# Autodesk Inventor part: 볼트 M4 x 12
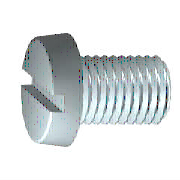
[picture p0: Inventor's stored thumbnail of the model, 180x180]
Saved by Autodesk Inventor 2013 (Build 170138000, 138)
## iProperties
Created: 2012-02
Part Number: 볼트 M4 x 12
Material: 강철, 연강
Description: 6각머리 태핑 나사
Document SubType Name: Modeling
Standard: KS B 1021
Designer: mduedu
Standards Organization: KS
Language: ko-KR
Size Designation: A  M 4 x 12
Categories: <MemberInstance><Categories><Category DisplayName="조임쇠" InternalName="e4da775c-781d-43d5-af7c-5136215cf5a6" Mnemonic="FSTN"><Category DisplayName="볼트" InternalN
Density: 1 g/cm^3
IsCustomPart: 0
Author: mduedu
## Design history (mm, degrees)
body "Solid1"
revolve "본체" stored, may be unused: angle "d8" = 90 deg
sketch "스케치2"
  geometry: L1 (0, 0)-(0, 3.273) reference; L2 (-3.5, 0.6)-(3.5, 0.6); L3 (3.5, 0.6)-(3.5, -0.6); L4 (3.5, -0.6)-(-3.5, -0.6); L5 (-3.5, -0.6)-(-3.5, 0.6); L6 (-3.5, 0)-(3.5, 0); L7 (0, 0.6)-(0, -0.6); C1 r 3.5 at (0, 0) reference; 1 further point
  constraints: 12 end point, 5 midpoint, 2 parallel, 1 collinear, 1 horizontal, 1 perpendicular
  dimensions: "d11" = 1.2 distance of L4.end L2.start (= SBR); "d12" = 7 distance of L2.start L2.end (= KOD)
fillet "모깎기1" dims "d14" = 0.2 (= RR)
extrude "슬롯" cut sketch "스케치2" distance "d19" = 1.1 (= STI); taper "d20" = 0 deg
feature "스레드" dims "d15" = 10.6 (= GEL), "d16" = 0
chamfer "모따기1" distance "d17" = 0.42941 (= -0.5 x SPD + 0.5 x GD); stored, may be unused: second distance "d18" = 0.42952 (computed from GUL), angle "d36" = 45 deg
workplane "Work Plane1"
sketch "스케치1"
  geometry: L1 (-2.6, 0)-(12, 0); L2 (12, 0)-(12, 2); L3 (12, 2)-(1.4, 2); L4 (1.4, 2)-(0.97, 1.785); L5 (0.97, 1.785)-(0, 1.785); L6 (0, 1.785)-(0, 3.5); L7 (-5.52, 0)-(14.92, 0) reference; L8 (0, -0.7)-(0, 4.2) reference; L9 (-2.6, 0)-(-2.6, 3.273); L10 (0, 3.5)-(-2.6, 3.273); L11 (1.4, 2)-(0, 2)
  constraints: 18 end point, 4 parallel, 2 collinear, 2 perpendicular, 1 horizontal, 1 point on line
  dimensions: "d0" = 12 distance between parallel lines of L2 L6 (= NLG); "d1" = 10.6 distance from line of L3.end L2 (= GEL); "d2" = 0.42952 horizontal distance of L4.end L3.end (computed from GAL); "d3" = 2.6 distance from line of L1.start L6 (= KOH); "d4" = 4 diameter of L3 L1 (= GD); "d5" = 3.5705 diameter of L5 L1 (= BDM); "d9" = 7 diameter of L6.end L1 (= KOD); "d10" = 5 deg angle of L10 L1 (= KEWI)
other parameters: "GD" = 4 (= NND) [user parameter; used in 2 equation terms], "NLG" = 12 [user parameter; used in 1 equation term], "GEL" = 10.6 [user parameter; used in 2 equation terms], "KOD" = 7 [user parameter; used in 2 equation terms], "KOH" = 2.6 [user parameter; used in 1 equation term], "GAL" = 0.42941 (= 0.61345 x PTC) [user parameter; used in 1 equation term], "SPD" = 3.14117 (= NND - 1.2269 x PTC) [user parameter; used in 1 equation term], "BDM" = 3.5705 [user parameter; used in 1 equation term], "GUL" = 0.42941 (= 0.61345 x PTC) [user parameter; used in 1 equation term], "RR" = 0.2 [user parameter; used in 1 equation term], "d7" = 0, "SBR" = 1.2 [user parameter; used in 1 equation term], "STI" = 1.1 [user parameter; used in 1 equation term], "KEWI" = 5 deg [user parameter; used in 1 equation term], "d37" = 0, "d39" = 0, "PTC" = 0.7 [user parameter; used in 5 equation terms], "THREADDIA" = 4 [user parameter; used in 1 equation term], "TOA" = 30 deg [user parameter], "TPU" = 14.28571 (computed from PTC) [user parameter], "NND" = 4 [user parameter; used in 2 equation terms], "GD1" = 3.14117 (= THREADDIA - 1.2269 x PTC) [user parameter]
